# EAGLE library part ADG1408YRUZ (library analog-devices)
4 Ohm RON, 8-Channel, ±15 V/+12 V/±5 V iCMOS Multiplexers Source: 8x ADG1408_1409.pdf
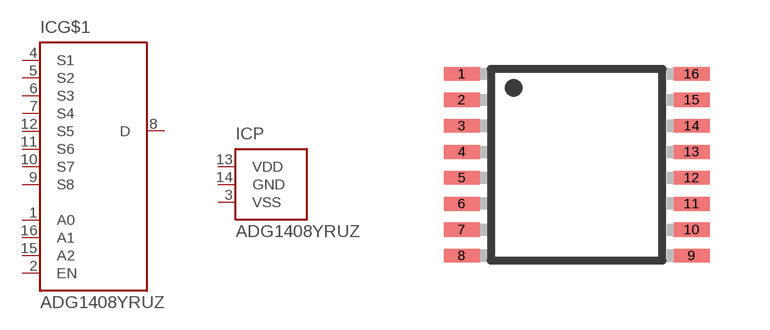
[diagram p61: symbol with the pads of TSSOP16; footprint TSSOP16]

Designator prefix IC; gates G$1=ADG1408 P=PWR-VSS_GND_VDD

## ADG1408YRUZ (MPN: ADG1408YRUZ; OC_FARNELL: 1438940; OC_NEWARK: 28M3586)  [TSSOP16]
1  G$1:A0  in
2  G$1:EN  in
3  P:VSS  pwr
4  G$1:S1
5  G$1:S2
6  G$1:S3
7  G$1:S4
8  G$1:D
9  G$1:S8
10  G$1:S7
11  G$1:S6
12  G$1:S5
13  P:VDD  pwr
14  P:GND  pwr
15  G$1:A2  in
16  G$1:A1  in

## Footprint TSSOP16 (pad centres in mm)
16-Lead Thin Shrink Small Outline Package [TSSOP] (RU-16) Source: 8x ADG1408_1409.pdf
smd 0.9 x 0.35: 1 -2.875,2.275; 2 -2.875,1.625; 3 -2.875,0.975; 4 -2.875,0.325; 5 -2.875,-0.325; 6 -2.875,-0.975; 7 -2.875,-1.625; 8 -2.875,-2.275; 9 2.875,-2.275; 10 2.875,-1.625; 11 2.875,-0.975; 12 2.875,-0.325; 13 2.875,0.325; 14 2.875,0.975; 15 2.875,1.625; 16 2.875,2.275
